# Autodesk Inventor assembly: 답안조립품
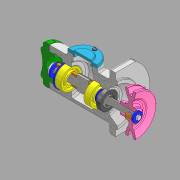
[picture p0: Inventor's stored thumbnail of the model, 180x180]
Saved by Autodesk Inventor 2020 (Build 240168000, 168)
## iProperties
Created: 2022-05
Part Number: 답안조립품
Document SubType Name: Assembly
Designer: User
Author: User
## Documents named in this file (22)
- C:\Users\User\Desktop\720506V1032\답안조립품.iam
- C:\Users\User\Desktop\720506V1032\01_본체.ipt
- C:\Users\User\Desktop\720506V1032\V-벨트풀리.ipt
- C:\Users\User\Desktop\720506V1032\개스킷.ipt
- C:\Users\User\Desktop\720506V1032\너트 M10.ipt
- C:\Users\User\Desktop\720506V1032\멈춤나사 M3.ipt
- C:\Users\User\Desktop\720506V1032\멈춤링 15 x 1.ipt
- C:\Users\User\Desktop\720506V1032\멈춤링 35 x 1.6.ipt
- C:\Users\User\Desktop\720506V1032\베어링 6202.ipt
- C:\Users\User\Desktop\720506V1032\볼트 M4 x 10.ipt
- C:\Users\User\Desktop\720506V1032\부시1.ipt
- C:\Users\User\Desktop\720506V1032\부시2.ipt
- C:\Users\User\Desktop\720506V1032\사이드 커버.ipt
- 사이드 커버.ipt
- C:\Users\User\Desktop\720506V1032\십자볼트 M3 x 10.ipt
- C:\Users\User\Desktop\720506V1032\오일 실 15 x 30 x 7.ipt
- C:\Users\User\Desktop\720506V1032\와셔 3 x 6.ipt
- C:\Users\User\Desktop\720506V1032\와셔 4 x 16.ipt
- C:\Users\User\Desktop\720506V1032\와셔 10 x 21.ipt
- C:\Users\User\Desktop\720506V1032\축.ipt
- C:\Users\User\Desktop\720506V1032\키 4 x 4.ipt
- C:\Users\User\Desktop\720506V1032\탑 커버.ipt
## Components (4 placed, 4 different names)
1. 01_본체:1 — 각도:1, 각도:2, 각도:3, 각도:4, 각도:5, 각도:12, 각도:14, 각도:15, drive
2. V-벨트풀리:1
3. 개스킷:1 — 각도:1
4. ISO 4017 M4 x 10:1 — 각도:17
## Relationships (10: Angle 10)
- 각도:1 [Angle]: 01_본체:1 ↔ 개스킷:1
- 각도:2 [Angle]: 01_본체:1
- 각도:3 [Angle]: 01_본체:1
- 각도:4 [Angle]: 01_본체:1
- 각도:5 [Angle]: 01_본체:1
- 각도:12 [Angle]: 01_본체:1
- 각도:14 [Angle]: 01_본체:1
- 각도:15 [Angle]: 01_본체:1
- 각도:17 [Angle]: ISO 4017 M4 x 10:1
- drive [Angle]: 01_본체:1
